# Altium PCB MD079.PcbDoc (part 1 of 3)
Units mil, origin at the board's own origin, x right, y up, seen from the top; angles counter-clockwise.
Board outline 4255 x 2850 mil, 4 copper layers (Top Layer, Ground, Power, Bottom Layer), stack 61.6 mil thick; 171 components, 88 nets, 422 pads, 405 vias.
Unrouted connection lines stored in the file: 3.
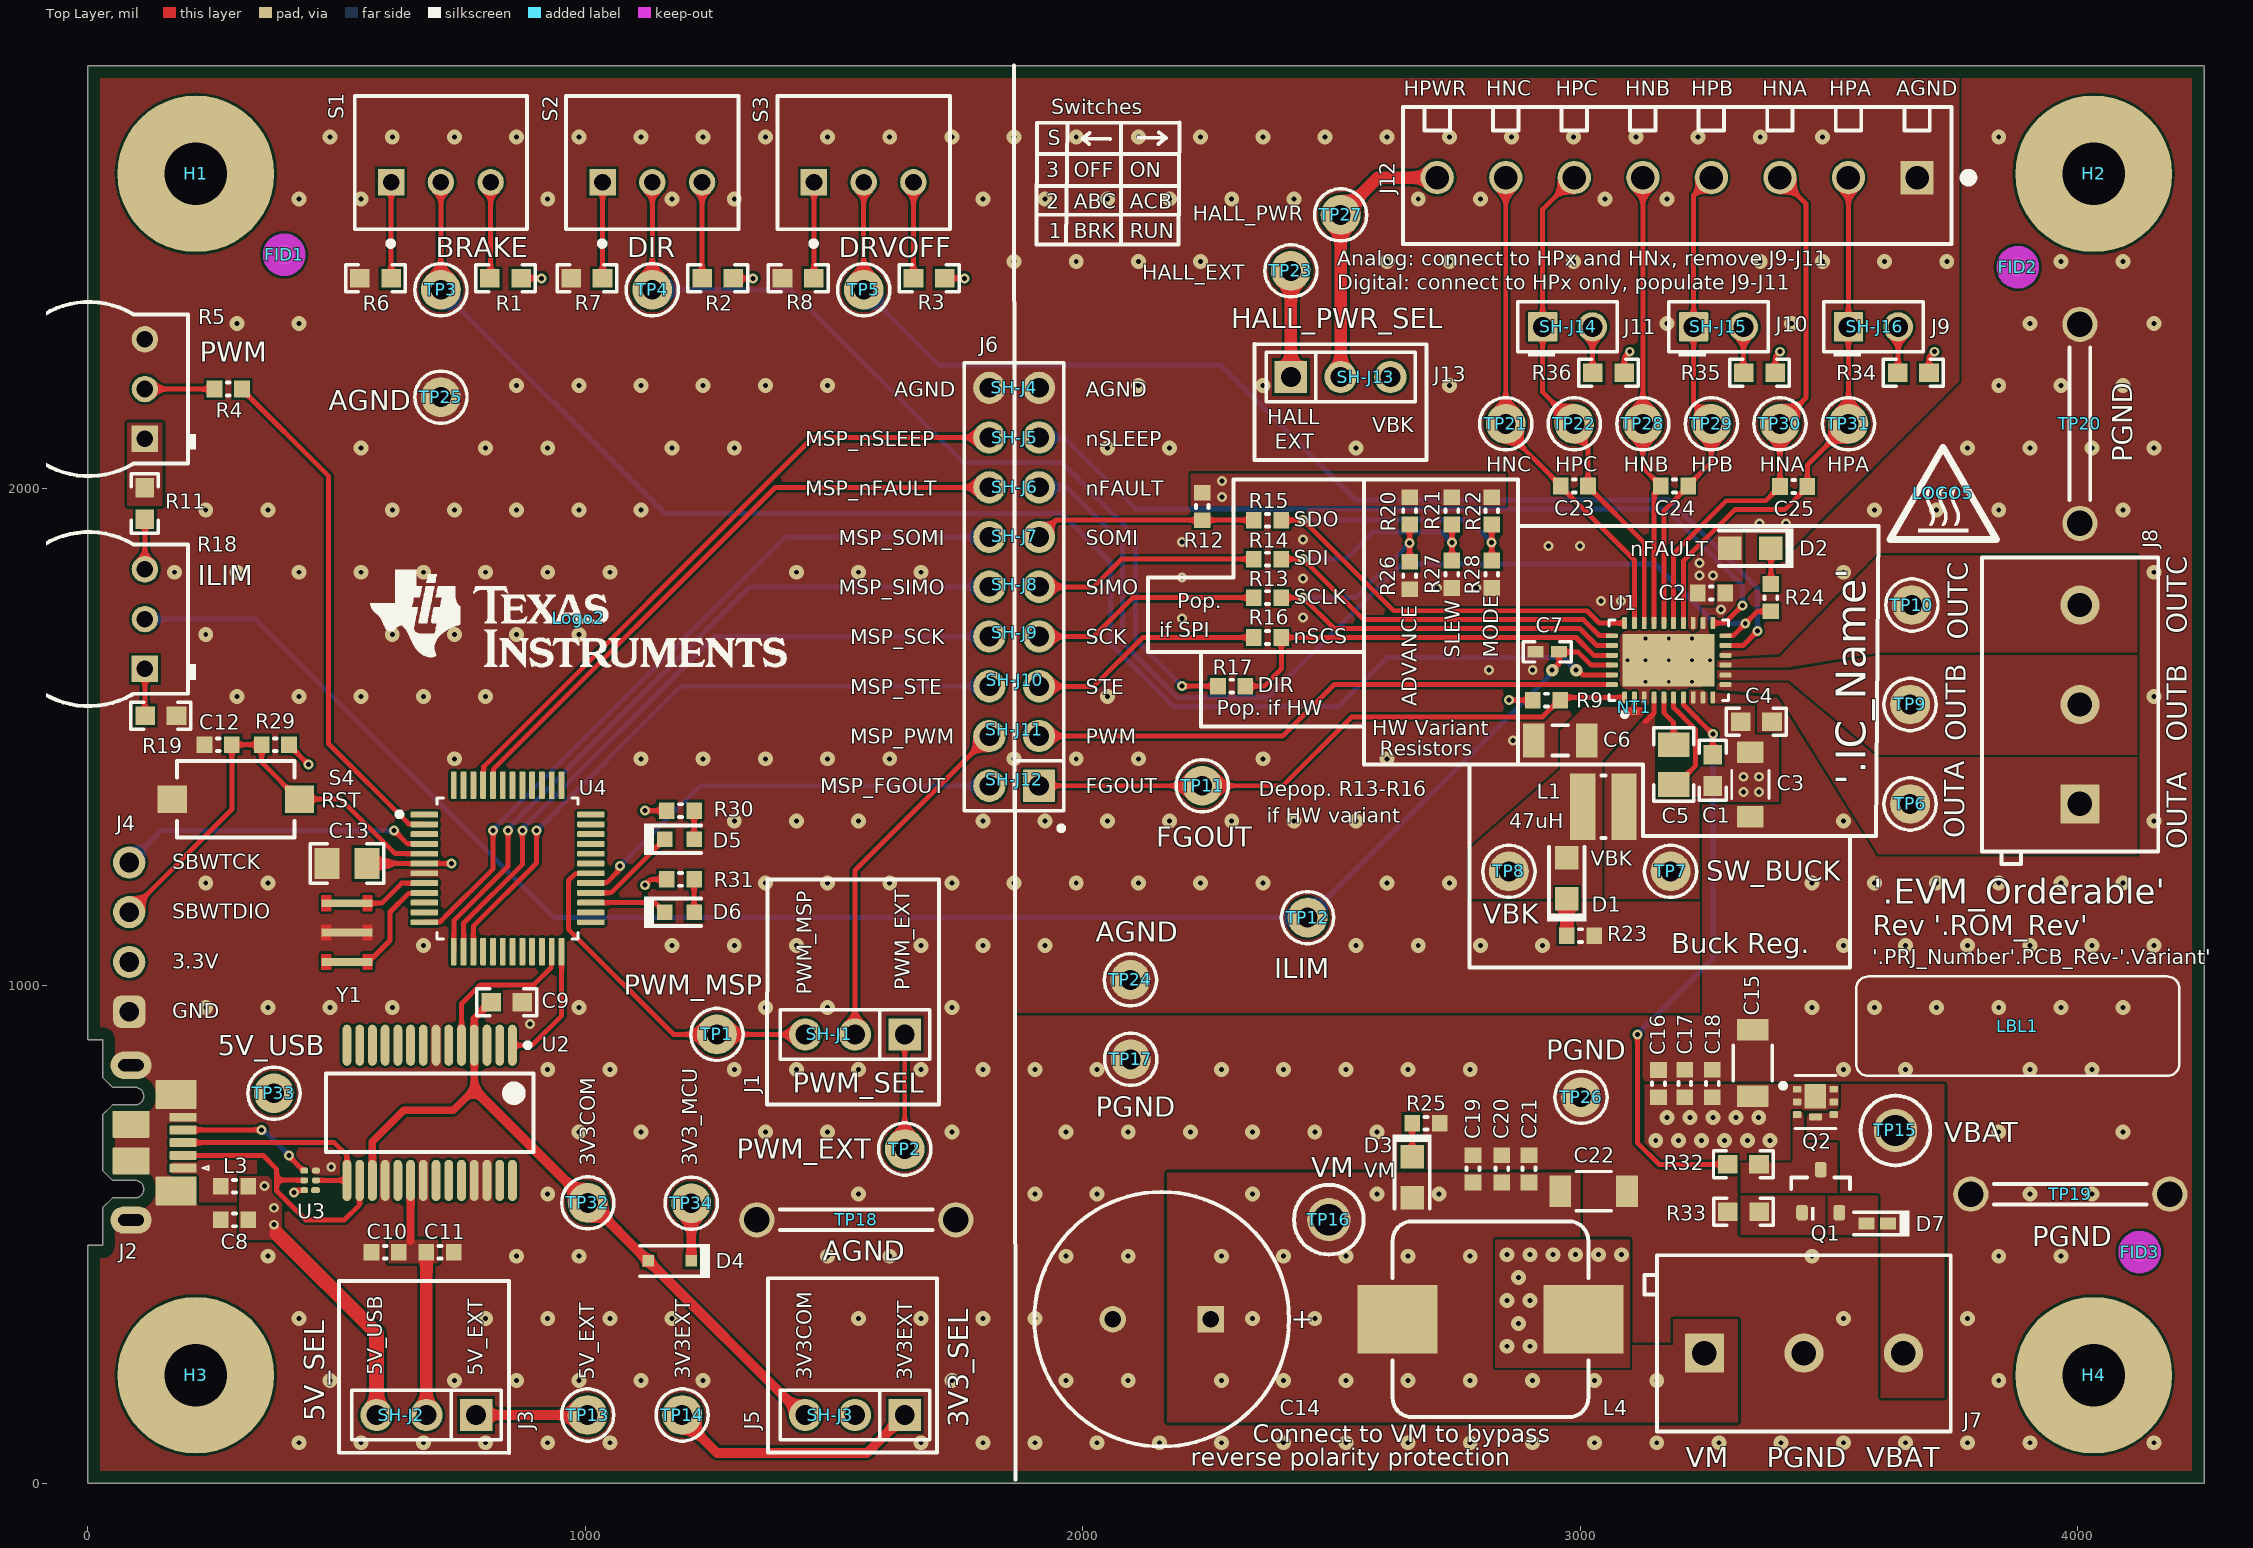
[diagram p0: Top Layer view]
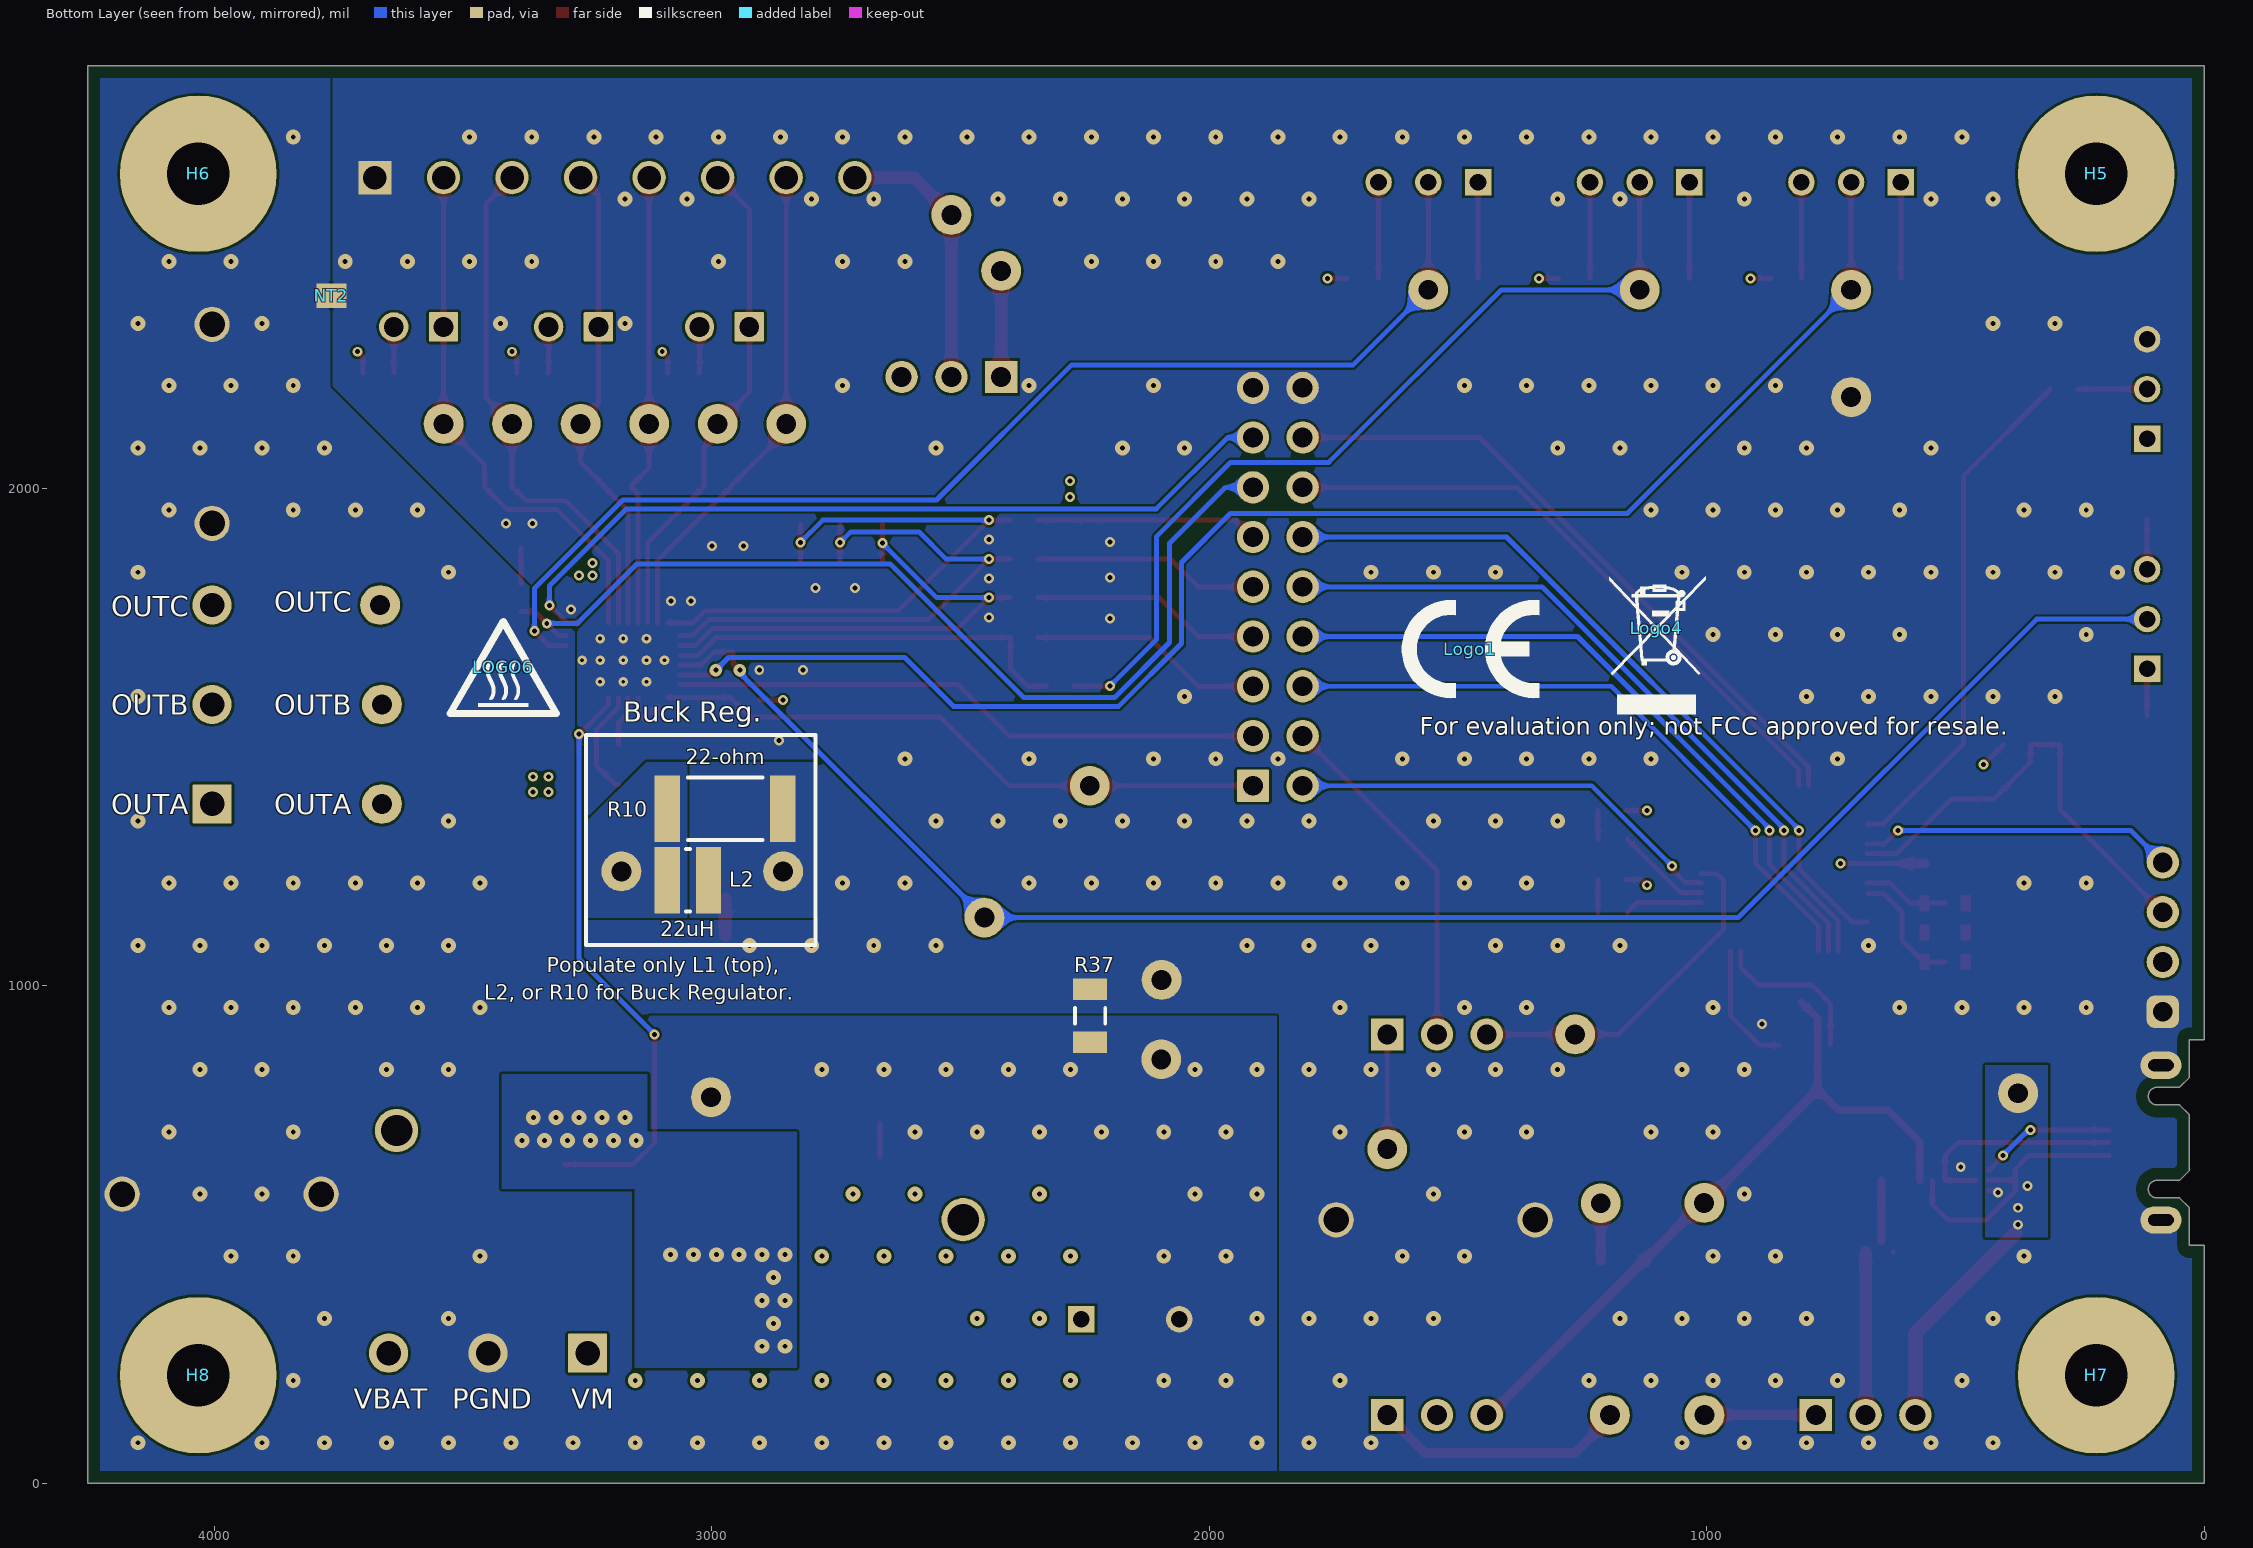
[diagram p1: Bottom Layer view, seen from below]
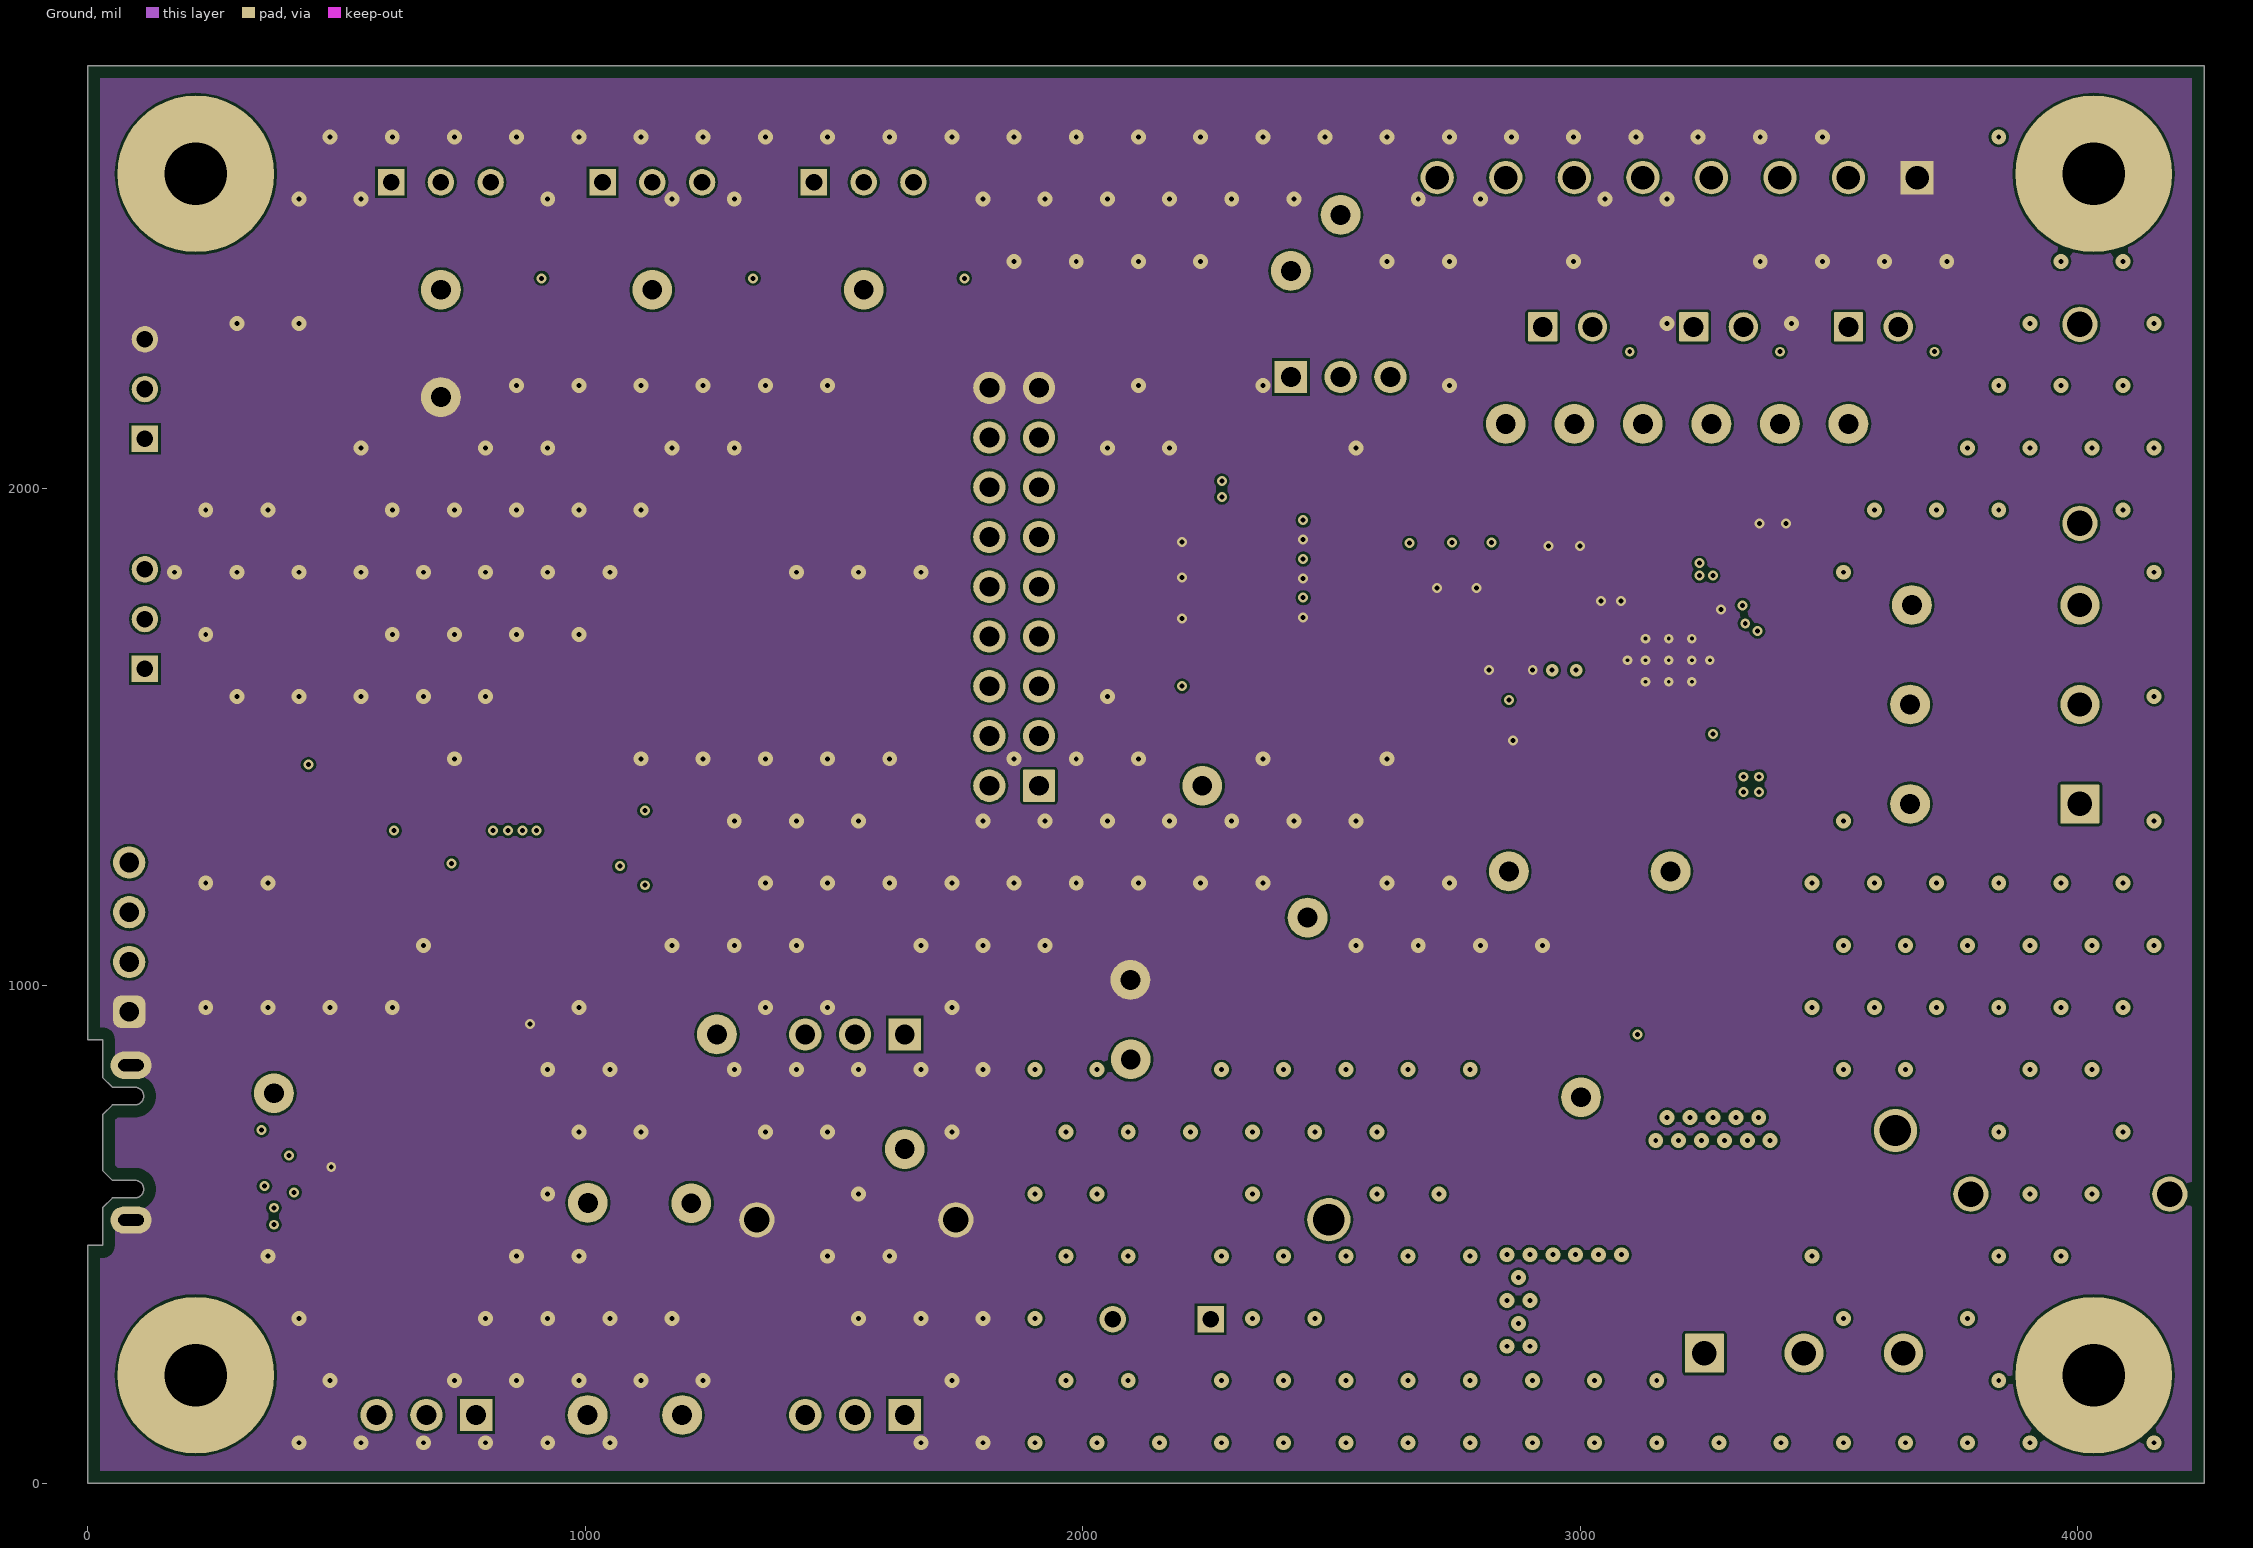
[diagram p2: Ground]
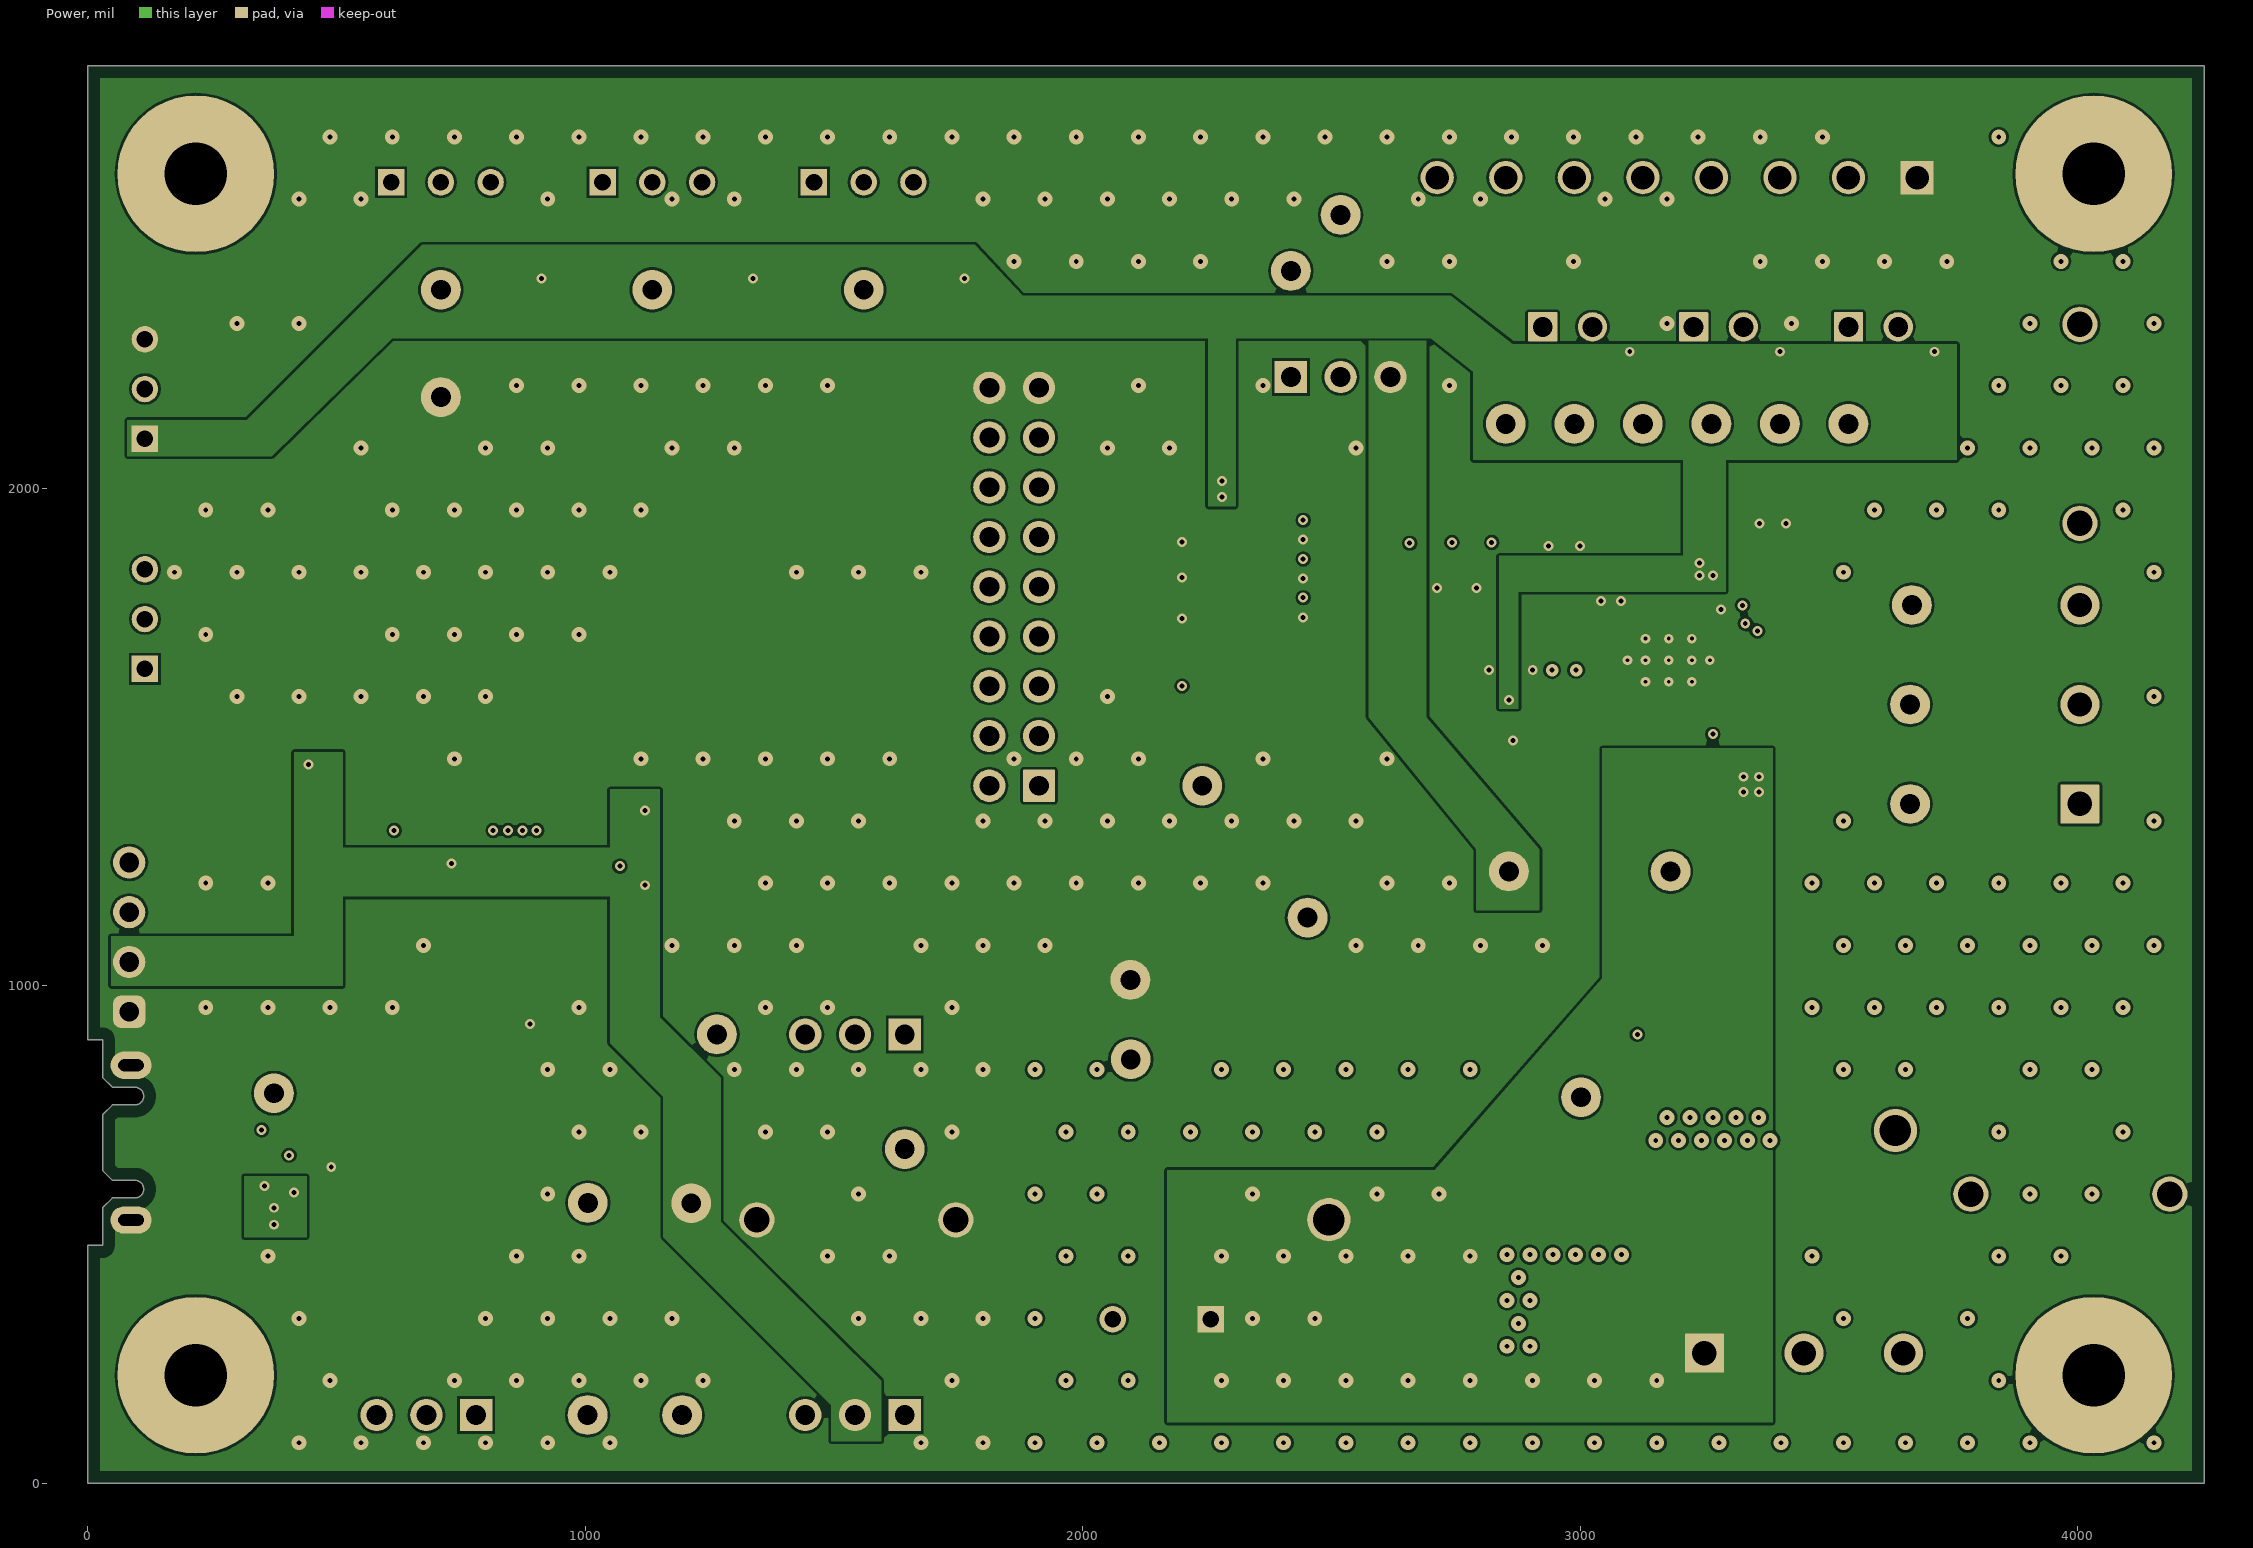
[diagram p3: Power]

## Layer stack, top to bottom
Top Solder: solder mask 0.4, Solder Resist, Dk 3.5
Top Layer: signal copper 1.4
Dielectric 1: prepreg 8, FR-4, Dk 4.2
Ground: signal copper 1.4
Dielectric 2: core 40, FR-4, Dk 4.2
Power: signal copper 1.4
Dielectric 3: prepreg 8, FR-4, Dk 4.2
Bottom Layer: signal copper 1.4
Bottom Solder: solder mask 0.4, Solder Resist, Dk 3.5

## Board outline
0,0 0,478.31 30,478.31 30,554.09 49.68,573.78 94.96,573.78 ccw(c94.81,591.5) 94.96,609.21 49.68,609.21 30,628.9 30,741.1 49.68,760.79 94.96,760.79 ccw(c94.85,778.5) 94.96,796.22 49.68,796.22 30,815.91 30,891.69 0,891.69 0,2850 4255,2850 4255,0

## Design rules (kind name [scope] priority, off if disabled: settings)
AcuteAngle [All] p1: minimum=4.50000000000000E+0001 checktracksonly=FALSE
AssemblyTestPointUsage [All] p1: valid=2
BoardOutlineClearance BoardOutlineClearance_MountingHoles [OnCopper and InComponentClass('Mounting Holes')] p1: gap=39.37 ignorepadtopadclearanceinfootprint=FALSE
BoardOutlineClearance BoardOutlineClearance_Poly [OnCopper and IsPoly] p2: gap=25 ignorepadtopadclearanceinfootprint=FALSE
BoardOutlineClearance [OnCopper and Not InComponentClass('Logo') and not InComponentClass('FiducialMark') and not InRegion(1000,500,4000,800) and not InPoly] p3: gap=30 ignorepadtopadclearanceinfootprint=FALSE
Clearance "Stitching AGND" [IsStitchingVia and InNet('AGND') vs (IsVia and (Not IsStitchingVia)) Or IsPad] p1: gap=70 ignorepadtopadclearanceinfootprint=TRUE
Clearance Clearance_Keepouts [((IsTrack Or IsArc) And Not InPoly) And IsFree and IsKeepOut vs ((IsTrack Or IsArc) And Not InPoly) And IsFree and IsKeepOut] p2: gap=0 ignorepadtopadclearanceinfootprint=FALSE
Clearance Clearance_Poly [InPolygon] p3: gap=5 ignorepadtopadclearanceinfootprint=TRUE
Clearance Clearance_FiducialMark [IsKeepOut and InComponentClass('FiducialMark') vs IsPad and InComponentClass('FiducialMark')] p4: gap=0 ignorepadtopadclearanceinfootprint=FALSE
Clearance [All] p5: gap=7.87 ignorepadtopadclearanceinfootprint=TRUE
ComponentClearance ComponentClearance_MountingHoles_FiducialMarks [InComponentClass('Mounting Holes') vs InComponentClass('FiducialMark')] p1: gap=50 collisioncheckmode=3 verticalgap=10 showdistances=FALSE
ComponentClearance ComponentClearance_Shunt [InComponentClass('Header') vs InComponentClass('Shunt')] p2: gap=0 collisioncheckmode=3 verticalgap=0 showdistances=FALSE
ComponentClearance ComponentClearance_Logo [InComponentClass('Logo')] p3: gap=50 collisioncheckmode=3 verticalgap=10 showdistances=FALSE
ComponentClearance ComponentClearance_ScrewToNut [(HasFootprint('NY PMS 440 0025 PH')) vs (HasFootprint('Keystone_1902C'))] p4: gap=5 collisioncheckmode=3 verticalgap=10 showdistances=FALSE
ComponentClearance ComponentClearance_MountingHoles [InComponentClass('Mounting Holes')] p5: gap=150 collisioncheckmode=3 verticalgap=100000 showdistances=FALSE
ComponentClearance ComponentClearance_SmallPassives [HasFootprint('0201*') or HasFootprint('0402*') or HasFootprint('0508') or HasFootprint('0603*') or HasFootprint('0612') or HasFootprint('0805*') or HasFootprint('0815*') or HasFootprint('0830*') or HasFootprint('1206*') or HasFootprint('1210*') or HasFootprint('1808*') or HasFootprint('1812*') or HasFootprint('1825*') or HasFootprint('2010*') or HasFootprint('2220*') or HasFootprint('2225*') or HasFootprint('2512*') or HasFootprint('2728*') or HasFootprint('3518*') vs HasFootprint('0201*') or HasFootprint('0402*') or HasFootprint('0508') or HasFootprint('0603*') or HasFootprint('0612') or HasFootprint('0805*') or HasFootprint('0815*') or HasFootprint('0830*') or HasFootprint('1206*') or HasFootprint('1210*') or HasFootprint('1808*') or HasFootprint('1812*') or HasFootprint('1825*') or HasFootprint('2010*') or HasFootprint('2220*') or HasFootprint('2225*') or HasFootprint('2512*') or HasFootprint('2728*') or HasFootprint('3518*')] p6: gap=14.96 collisioncheckmode=3 verticalgap=10 showdistances=FALSE
ComponentClearance ComponentClearance_THtoSMT [IsThruComponent vs IsSMTComponent] p7: gap=0 collisioncheckmode=3 verticalgap=0 showdistances=FALSE
ComponentClearance ComponentClearance_THtoTH [IsThruComponent vs IsThruComponent] p8: gap=0 collisioncheckmode=3 verticalgap=0 showdistances=FALSE
ComponentClearance [All] p9: gap=0 collisioncheckmode=3 verticalgap=0 showdistances=FALSE
DiffPairsRouting [All] p1: maxlimit=100 minlimit=10 mostfreqgap=10 toplayer_minwidth=15 toplayer_maxwidth=15 toplayer_prefwidth=15 midlayer1_minwidth=15 midlayer1_maxwidth=15 midlayer1_prefwidth=15 midlayer2_minwidth=15 midlayer2_maxwidth=15 midlayer2_prefwidth=15 bottomlayer_minwidth=15 bottomlayer_maxwidth=15 bottomlayer_prefwidth=15 maxuncoupledlength=1000
FabricationTestPointUsage TestPointUsage [All] p1: valid=2 allowmultiple=FALSE
FabricationTestpoint Testpoint [All] p1: side=3 testpointundercomponent=TRUE minsize=40 maxsize=100 preferedsize=60 minholesize=0 maxholesize=40 preferedholesize=32 testpointgrid=1 allowsidetop=TRUE allowsidebottom=TRUE usegrid=TRUE gridtolerance=0.01
FanoutControl Fanout_LCC [IsLCC] p1: bgadir=Out bgaviamode=Centered fanoutstyle=Auto fanoutdirection=Alternating viagrid=1 // Fanout_LCC (Default Rule)
FanoutControl Fanout_BGA [IsBGA] p2: bgadir=Out bgaviamode=Centered fanoutstyle=Auto fanoutdirection=Alternating viagrid=1 // Fanout_BGA (Default Rule)
FanoutControl Fanout_Default [All] p4: bgadir=Out bgaviamode=Centered fanoutstyle=Auto fanoutdirection=Alternating viagrid=1 // Fanout_Default (Default Rule)
FanoutControl Fanout_Small [(CompPinCount < 5)] p5: bgadir=Out bgaviamode=Centered fanoutstyle=Auto fanoutdirection=OutThenIn viagrid=1 // Fanout_Small (Default Rule)
HoleSize [All] p1: absolutevalues=TRUE maxlimit=200 minlimit=1 maxpercent=80.000 minpercent=20.000
MinimumAnnularRing MinimumAnnularRing_ThermalPadVias [IsVia and InAnyComponent] p1: minimumring=1
MinimumAnnularRing [All] p2: minimumring=1
MinimumSolderMaskSliver MinimumSolderMaskSliver_Logo [InComponentClass('Logo') vs InComponentClass('Logo')] p1: minsoldermaskwidth=0.7
MinimumSolderMaskSliver [All] p2: minsoldermaskwidth=1
PlaneConnect [All] p1: planeconnectstyle=Relief reliefexpansion=10 reliefentries=4 reliefconductorwidth=10 reliefairgap=10
PolygonConnect [All] p1: connectstyle=Direct reliefconductorwidth=10 reliefentries=4 polygonreliefangle="90 Angle" airgapwidth=10
RoutingVias ThermalPadVias [IsVia and InAnyComponent] p1: holewidth=7.87 width=19.68 viastyle="Through Hole" minholewidth=7.87 minwidth=19.68 maxholewidth=12.99 maxwidth=23.62
RoutingVias [All] p2: holewidth=10 width=25 viastyle="Through Hole" minholewidth=7 minwidth=20 maxholewidth=15 maxwidth=30
SilkToBoardRegionClearance [Not ((IsComment or IsDesignator) And (Hide <> 'False')) and not InRegion(1000,500,4000,800)] p1:
SilkToSilkClearance SilkToSilkClearance_Pb-FreeLogo [(HasFootprint('Pb-Free_Overlay_Medium') OR HasFootprint('Pb-Free_Overlay_Small')) vs (HasFootprint('Pb-Free_Overlay_Medium') OR HasFootprint('Pb-Free_Overlay_Small'))] p1: silktosilkclearance=1
SilkToSilkClearance [All] p2: silktosilkclearance=1
SilkToSolderMaskClearance [IsPad] p1: minsilkscreentomaskgap=1 clearancetoexposedcopper=TRUE
SolderMaskExpansion [All] p1: expansion=1.97 istentingtop=FALSE
UnRoutedNet [All] p1: checkbadconnections=TRUE
Width [All] p1: maxlimit=100 minlimit=6 preferedwidth=10 checkconnectedcopper=TRUE
14 further rules are at their usual default settings.

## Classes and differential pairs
component class Label: LBL1
component class "Mounting Holes": H1 H2 H3 H4
component class MD079_INTERFACE: 3V3_EXT C8 C9 C10 C11 C12 C13 D4 D5 D6 J2 J3 J4 J5 J6 L3 R29 R30 R31 S4 SH-J2 SH-J3 SH-J4 SH-J5 SH-J6 SH-J7 SH-J8 SH-J9 SH-J10 SH-J11 SH-J12 TP13 TP14 TP32 TP33 TP34 U2 U3 U4 Y1
component class MD079_CONTROL: J1 R1 R2 R3 R4 R5 R6 R7 R8 S1 S2 S3 SH-J1 TP1 TP2 TP3 TP4 TP5
component class Shunt: SH-J1 SH-J2 SH-J3 SH-J4 SH-J5 SH-J6 SH-J7 SH-J8 SH-J9 SH-J10 SH-J11 SH-J12 SH-J13 SH-J14 SH-J15 SH-J16
component class MD079_POWER_AND_CONNECTORS: AGND1 C14 C15 C16 C17 C18 C19 C20 C21 C22 C23 C24 C25 D7 J7 J8 J9 J10 J11 J12 J13 L4 NT2 PGND PGND2 Q1 Q2 R32 R33 R34 R35 R36 R37 R45 SH-J13 SH-J14 SH-J15 SH-J16 TP15 TP16 TP17 TP18 TP19 TP20 TP21 TP22 TP23 TP24 TP25 TP26 TP27 TP28 TP29 TP30 TP31 vm VM1
component class MD079_DRIVER: 1 A1 B1 C1 C2 C3 C4 C5 C6 C7 D1 D2 D3 D? ILIM1 L1 L2 NT1 R9 R10 R11 R12 R13 R14 R15 R16 R17 R18 R19 R20 R21 R22 R23 R24 R25 R26 R27 R28 TP6 TP7 TP8 TP9 TP10 TP11 TP12 U1
component class Header: J1 J3 J4 J5 J6 J9 J10 J11 J13
component class Logo: Logo2
component class MD079_HARDWARE: FID1 FID2 FID3 H1 H2 H3 H4 H5 H6 H7 H8 LBL1 Logo1 Logo2 Logo3 Logo4 LOGO5 LOGO6 ZZ1 ZZ2 ZZ3 ZZ4
component class FiducialMark: FID1 FID2 FID3
component class AssemblyNote: ZZ1 ZZ2 ZZ3 ZZ4

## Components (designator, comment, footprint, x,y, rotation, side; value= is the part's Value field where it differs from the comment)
C1 "0603YD105KAT2A" 0603 3266.91,1433.54 r270 top value=1uF
C2 "C0603C105K9RACAUTO" 0603L 3264.11,1790 r180 top value=1uF
C3 "C3216X6S2A106K160AC" FP-C3216X6S2A106K160AC_1206-MFG 3342.44,1405 r90 top value=10µF
C4 "GCJ188R72A104KA01D" 0603 3354.41,1531.45 r0 top value=0.1uF
C5 "C2012X7R2A473K125AA" 0805_HV 3188.17,1445 r90 top value=0.047uF
C6 "GRM31CR71A226KE15L" 1206_180L 2960.57,1493.52 r180 top value=22uF
C7 "C1005X5R1A104K050BA" 0402 2934.02,1671.75 r180 top value=0.1uF
C8 "C0603C104K8RACTU" 0603L 295.3,529.83 r180 top value=0.1uF
C9 "C0603C104K8RACTU" 0603 842.5,967.5 r0 top value=0.1uF
C10 "GRM188Z71A475ME15D" 0603L 597.93,464.83 r0 top value=4.7uF
C11 "C0603C104K8RACTU" 0603L 708.38,464.83 r0 top value=0.1uF
C12 "885012206034" 0603L 262.36,1485.08 r180 top value=1000pF
C13 "C0805C105K5RACTU" 0805_HV 521.16,1246.18 r180 top value=1uF
C14 "ELXZ630ELL331MK20S" Chemi-Con_1250x2000 2159.07,330 r180 top value=330uF
C15 "GRM31CR72A105KA01L" 1206_180 3347.22,845.06 r90 top value=1uF
C16 "CGA3E3X7S2A104K080AB" 0603L 3157.89,803.52 r90 top value=0.1uF
C17 "CGA3E2X7R2A103K080AA" 0603L 3210.43,803.77 r90 top value=0.01uF
C18 "06031C102JAT2A" 0603L 3266.18,803.88 r90 top value=1000pF
C19 "06031C102JAT2A" 0603L 2785,632.45 r90 top value=1000pF
C20 "CGA3E2X7R2A103K080AA" 0603L 2842.95,632.45 r90 top value=0.01uF
C21 "CGA3E3X7S2A104K080AB" 0603L 2897.5,632.45 r90 top value=0.1uF
C22 "GRM31CR72A105KA01L" 1206_180 3027.5,587.55 r0 top value=1uF
C23 "0603YC104K4T4A" 0603L 2988.52,2005 r0 top value=0.1uF
C24 "0603YC104K4T4A" 0603L 3189.74,2005 r0 top value=0.1uF
C25 "0603YC104K4T4A" 0603L 3429.47,2004.02 r0 top value=0.1uF
D1 "LTST-C170KGKT" LTST-C170KGKT_Green 2973.39,1216.38 r270 top value=Green
D2 "LTST-C170KRKT" LED_LTST-C170_Red 3342.44,1880 r0 top value=Red
D3 "LTST-C170KGKT" LTST-C170KGKT_Green 2662.52,615.11 r90 top value=Green
D4 "BAT165E6327HTSA1" SOD-323 1170,447.36 r180 top value=40V
D5 "LTST-C190KRKT" LED_LTST-C190_Red 1189.52,1295.15 r180 top value=Red
D6 "LTST-C190GKT" LED_LTST-C190 1189.52,1148.04 r180 top value=Green
D7 "BAS516,115" SOD-523 3597.5,522.5 r180 top value=100V
FID1 "Fiducial" Fiducial10-20 395,2470 r0 top
FID2 "Fiducial" Fiducial10-20 3880,2445 r0 top
FID3 "Fiducial" Fiducial10-20 4125,465 r0 top
H1 "NY PMS 440 0025 PH" "NY PMS 440 0025 PH" 217.5,2632.5 r0 top
H2 "NY PMS 440 0025 PH" "NY PMS 440 0025 PH" 4032.5,2632.5 r0 top
H3 "NY PMS 440 0025 PH" "NY PMS 440 0025 PH" 217.5,217.5 r0 top
H4 "NY PMS 440 0025 PH" "NY PMS 440 0025 PH" 4032.5,217.5 r0 top
H5 "Nut" Keystone_1902C 217.5,2632.5 r180 bottom
H6 "Nut" Keystone_1902C 4032.5,2632.5 r180 bottom
H7 "Nut" Keystone_1902C 217.5,217.5 r180 bottom
H8 "Nut" Keystone_1902C 4032.5,217.5 r180 bottom
J1 "Header_3x1" PBC03SAAN 1542.5,902.5 r180 top
J2 "1051640001" Molex_1051640001 30,685 r270 top
J3 "Header_3x1" PBC03SAAN 680.89,137.5 r180 top
J4 "TSW-104-07-G-S" TSW-104-07-G-S 83.45,1098.24 r90 top
J5 "Header_3x1" PBC03SAAN 1542.5,137.5 r180 top
J6 "TSW-109-07-G-D" Samtec_TSW-109-07-G-D 1862.5,1802.5 r90 top
J7 "MOTOR_OUT" On-Shore_ED120_3DS 3450,261.84 r0 top
J8 "MOTOR_OUT" On-Shore_ED120_3DS 4005,1565.83 r90 top
J9 "PEC02SAAN" CONN_PEC02SAAN 3589.65,2325 r0 top
J10 "PEC02SAAN" CONN_PEC02SAAN 3278.33,2325 r0 top
J11 "PEC02SAAN" CONN_PEC02SAAN 2975,2325 r0 top
J12 "OSTTE080161" On-Shore_OSTTE080161 3195.22,2625 r180 top
J13 "HALL_PWR_SEL" PBC03SAAN 2518.77,2224.15 r0 top
L1 "78438335470" WE-MAIA_3015 3047.07,1360.21 r180 top value=47uH
L2 "78438335220" WE-MAIA_3015 3048.37,1212.41 r180 bottom value=22uH
L3 "BLM18SG121TZ1D" 0603L 295,597.5 r180 top
L4 "SRP1038A-1R0M" SRP1038A 2820,330 r180 top value=1uH
LBL1 "THT-14-423-10" Label_650x200 3880,919.08 r0 top
Logo1 "CE Mark" CE_Mark_5mm 1475.24,1677.22 r180 bottom
Logo2 "Texas Instruments" TI_Stacked_Overlay_Small 986.72,1739.02 r0 top
Logo3 "FCC disclaimer" FCC_disclaimer 2440,3370 r90 top
Logo4 "WEEE logo" WEEE_Minimum 1101.22,1718.72 r180 bottom
LOGO5 "CAUTION HOT SURFACE" IEC_HotSurface_Small 3729.98,1990.63 r0 top
LOGO6 "CAUTION HOT SURFACE" IEC_HotSurface_Small 3419.55,1640.41 r180 bottom
NT1 "Net-Tie" Net-Tie_10mil 3109.32,1560.44 r270 top net-tie
NT2 "Net-Tie" Net-Tie_50milWide_30milLong 3765,2387.5 r0 bottom net-tie
Q1 "FMMT620TA" SOT-23L 3483.75,587.55 r90 top value="80 V"
Q2 "BUK9D23-40EX" FP-BUK9D23-40EX_SOT1220-MFG 3473.19,766.91 r0 top
R1 "RC0603FR-0710KL" 0603 840,2422.5 r0 top value=10.0k
R2 "RC0603FR-0710KL" 0603 1266.52,2422.52 r0 top value=10.0k
R3 "RC0603FR-0710KL" 0603 1691.66,2422.64 r0 top value=10.0k
R4 "ERJ-3GEY0R00V" 0603L 282.5,2200 r180 top value=0
R5 "3352T-1-253LF" Bourns_3352T 115,2200 r90 top value=25k
R6 "RC0603FR-0710KL" 0603 578.41,2422.48 r0 top value=10.0k
R7 "RC0603FR-0710KL" 0603 1003.46,2422.52 r0 top value=10.0k
R8 "RC0603FR-0710KL" 0603 1428.34,2422.64 r0 top value=10.0k
R9 "CRCW06035K10JNEA" 0603L 2932.5,1574.6 r180 top value=5.1k
R10 "CRCW251222R0JNEGHP" 2512 2973.57,1356.21 r180 bottom value=22
R11 "RC0603FR-0751K1L" 0603 115,1970 r90 top value=51.1k
R12 "CRCW06035K10JNEA" 0603L 2240.61,1963.92 r90 top value=5.1k
R13 "ERJ-3GEY0R00V" 0603L 2371.95,1780.64 r0 top value=0
R14 "ERJ-3GEY0R00V" 0603L 2371.95,1858.14 r0 top value=0
R15 "ERJ-3GEY0R00V" 0603L 2371.95,1936.33 r0 top value=0
R16 "ERJ-3GEY0R00V" 0603L 2371.95,1700.64 r0 top value=0
R17 "ERJ-3GEY0R00V" 0603L 2299.63,1602.81 r0 top value=0
R18 "3352T-1-103LF" Bourns_3352T 115,1737.5 r90 top value=10k
R19 "RC0603FR-0741K2L" 0603 147.01,1543.35 r180 top value=41.2k
R20 "ERA-3AEB104V" 0603L 2657.5,1955.2 r90 top value=100k
R21 "ERJ-3GEY0R00V" 0603L 2742.5,1955.2 r90 top value=0
R22 "ERJ-3EKF2202V" 0603L 2822.5,1955.2 r90 top value=22.0k
R23 "RC0603FR-07330RL" 0603L 3000.95,1101.26 r180 top value=330
R24 "RC0603JR-071KL" 0603L 3383.78,1780.64 r90 top value=1.0k
R25 "RT0603BRD074K7L" 0603L 2690.28,724.11 r180 top value=4.70k
R26 "ERJ-3GEY0R00V" 0603L 2657.5,1824.94 r90 top value=0
R27 "ERJ-3GEY0R00V" 0603L 2742.5,1827.74 r90 top value=0
R28 "ERA-3AEB104V" 0603L 2822.5,1827.74 r90 top value=100k
R29 "RC0603JR-0747KL" 0603L 377.2,1485.08 r0 top value=47k
R30 "RC0603JR-07470RL" 0603L 1191.51,1352.5 r180 top value=470
R31 "RC0603JR-07470RL" 0603L 1191.51,1214.26 r180 top value=470
R32 "RC0603FR-0710KL" 0603 3328.33,641.48 r0 top value=10.0k
R33 "RC0603FR-0710KL" 0603 3328.5,545.84 r0 top value=10.0k
R34 "RC0603FR-0710KL" 0603 3670,2232.5 r180 top value=10.0k
R35 "RC0603FR-0710KL" 0603 3361,2232.5 r180 top value=10.0k
R36 "RC0603FR-0710KL" 0603 3057.5,2232.5 r180 top value=10.0k
R37 "RCA12060000ZSEA" 1206L 2240,940 r270 bottom value=0
S1 "SW_SPDT_COM2_1_3" SW_B12AP 710,2655 r90 top
S2 "SW_SPDT_COM2_1_3" SW_B12AP 1135,2655 r90 top
S3 "SW_SPDT_COM2_1_3" SW_B12AP 1560,2655 r90 top
S4 "SW_SPST-single" SW_434121025816 297.8,1375.44 r180 top
SH-J1 "SNT-100-BK-G" SNT-100-BK-G 1491.17,902.5 r180 top value=1x2
SH-J2 "SNT-100-BK-G" SNT-100-BK-G 630.83,137.5 r180 top value=1x2
SH-J3 "SNT-100-BK-G" SNT-100-BK-G 1492.5,137.5 r180 top value=1x2
SH-J4 "SNT-100-BK-G" SNT-100-BK-G 1862.5,2202.5 r180 top value=1x2
SH-J5 "SNT-100-BK-G" SNT-100-BK-G 1863.16,2102.5 r180 top value=1x2
SH-J6 "SNT-100-BK-G" SNT-100-BK-G 1863.25,2002.5 r180 top value=1x2
SH-J7 "SNT-100-BK-G" SNT-100-BK-G 1863.33,1904 r180 top value=1x2
SH-J8 "SNT-100-BK-G" SNT-100-BK-G 1863.42,1806.72 r180 top value=1x2
SH-J9 "SNT-100-BK-G" SNT-100-BK-G 1863.5,1710.3 r180 top value=1x2
SH-J10 "SNT-100-BK-G" SNT-100-BK-G 1863.59,1615 r180 top value=1x2
SH-J11 "SNT-100-BK-G" SNT-100-BK-G 1862.5,1515 r180 top value=1x2
SH-J12 "SNT-100-BK-G" SNT-100-BK-G 1862.5,1415 r180 top value=1x2
SH-J13 "SNT-100-BK-G" SNT-100-BK-G 2569.13,2224.15 r180 top value=1x2
SH-J14 "SNT-100-BK-G" SNT-100-BK-G 2976.32,2325 r180 top value=1x2
SH-J15 "SNT-100-BK-G" SNT-100-BK-G 3277.5,2325 r180 top value=1x2
SH-J16 "SNT-100-BK-G" SNT-100-BK-G 3592.15,2325 r180 top value=1x2
TP1 "PWM_MSP" Keystone5002 1264.93,902.5 r90 top
TP2 "PWM_EXT" Keystone5002 1642.5,672.2 r90 top
TP3 "BRAKE" Keystone5002 710,2399.51 r90 top
TP4 "DIR" Keystone5002 1135,2399.51 r90 top
TP5 "DRVOFF" Keystone5002 1560,2399.51 r90 top
TP6 "OUTA" Keystone5000 3663.5,1365.83 r90 top
TP7 "SW_BUCK" Keystone5000 3182.09,1230.21 r90 top
TP8 "VBK" Keystone5000 2857.07,1230.21 r90 top
TP9 "OUTB" Keystone5000 3663.5,1565.83 r90 top
TP10 "OUTC" Keystone5000 3667.15,1765.83 r90 top
TP11 "FGOUT" Keystone5002 2240.64,1402.5 r90 top
TP12 "ILIM" Keystone5002 2452.32,1137.5 r90 top
TP13 "5V_EXT" Keystone5000 1005.02,137.5 r90 top
TP14 "3V3EXT" Keystone5000 1195,137.5 r90 top
TP15 "VBAT" Keystone5005 3634.05,709.46 r180 top
TP16 "VM" Keystone5005 2495,530.11 r0 top
TP17 "PGND" Keystone5001 2096.74,852.5 r90 top
TP18 "AGND" Harwin_D3082-05 1545.19,529.83 r180 top
TP19 "PGND" Harwin_D3082-05 3985.61,581.39 r180 top
TP20 "PGND" Harwin_D3082-05 4005,2130 r90 top
TP21 "HNC" Keystone5002 2850.73,2130 r90 top
TP22 "HPC" Keystone5002 2988.52,2130 r90 top
TP23 "HALL_EXT" Keystone5000 2418.77,2437.5 r90 top
TP24 "AGND" Keystone5001 2096.19,1012.13 r90 top
TP25 "AGND" Keystone5001 710,2183.75 r90 top
TP26 "PGND" Keystone5001 3002.02,776.25 r90 top
TP27 "HALL_PWR" Keystone5000 2518.77,2550 r90 top
TP28 "HNB" Keystone5002 3126.32,2130 r90 top
TP29 "HPB" Keystone5002 3264.11,2130 r90 top
TP30 "HNA" Keystone5002 3401.91,2130 r90 top
TP31 "HPA" Keystone5002 3539.65,2130 r270 top
TP32 "3V3COM" Keystone5000 1005.39,563.83 r90 top
TP33 "5V_USB" Keystone5000 374.4,784.37 r90 top
TP34 "3V3_MCU" Keystone5000 1213.31,563.23 r90 top
U1 "MCT8315Z0RRRYR" RRY0032A-MFG 3178.33,1654.84 r90 top
U2 "FT232RL" SSOP28_N 687.5,745 r270 top
U3 "TPD4E004DRYR" DRY0006A 447.16,609.17 r180 top
U4 "MSP430FR2355TPTR" PT0048A-MFG 844.22,1236.34 r0 top
Y1 "CSTCR4M00G55B-R0" Murata_CSTCR_G 521.16,1107.3 r270 top
ZZ1 "This Assembly Note is for PCB labels only" AssemblyNoteLabel -624.68,3416.2 r0 top
ZZ2 "These assemblies are ESD sensitive, ESD precautions shall be observed." AssemblyNote -624.68,3307.32 r0 top
ZZ3 "These assemblies must be clean and free from flux and all contaminants. Use of no clean flux is not acceptable." AssemblyNote -624.68,3218.76 r0 top
ZZ4 "These assemblies must comply with workmanship standards IPC-A-610 Class 2, unless otherwise specified." AssemblyNote -624.68,3130.2 r0 top

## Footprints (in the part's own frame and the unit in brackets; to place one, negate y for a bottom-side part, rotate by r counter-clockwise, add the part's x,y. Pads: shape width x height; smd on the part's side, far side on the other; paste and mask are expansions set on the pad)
0402 [mm] "0402 from SM-752 data"
  rect 0.8x0.6 smd: 1(-0.6,0) 2(0.6,0)
  silkscreen extent -1.22,-0.52 1.22,0.52, body extent -0.55,-0.3 0.55,0.3, height 0.6
0603 [mm] "0603 from SM-752 data"
  rect 1x0.95 smd: 1(-0.8,0) 2(0.8,0)
  silkscreen extent -1.52,-0.69 1.52,0.69, body extent -0.87,-0.47 0.87,0.47, height 1
0603L [mm] "0603 from SM-752 data"
  rect 0.8x0.85 smd: 1(-0.7,0) 2(0.7,0)
  silkscreen extent -0.07,-0.33 0.07,0.33, body extent -0.87,-0.47 0.87,0.47, height 1
0805_HV [mil] "0805 with 30mil clearance between pads"
  rect 50x63 smd: 1(-40,0) 2(40,0)
  silkscreen extent -74,-40 74,40, body extent -43,-29 43,29, height 57
1206_180 [mm] "1206_180"
  rect 1.1x1.6 smd: 1(-1.7,0) 2(1.7,0)
  silkscreen extent -0.9,-1 0.9,1, body extent -1.75,-0.95 1.75,0.95, height 1.8
1206_180L [mm] "1206_180"
  rect 1.1x1.75 smd: 1(-1.35,0) 2(1.35,0)
  silkscreen extent -0.4,-0.77 0.4,0.77, body extent -1.75,-0.95 1.75,0.95, height 1.8
1206L [mm] "1206 from SM-752 data"
  rect 1.1x1.75 smd: 1(-1.35,0) 2(1.35,0)
  silkscreen extent -0.4,-0.77 0.4,0.77, body extent -1.7,-0.9 1.7,0.9, height 1.35
2512 [mm] "Chip Resistor, Body 6.3x3.2mm, IPC Medium Density"
  rect 1.3x3.4 smd: 1(-2.95,0) 2(2.95,0)
  silkscreen extent -1.9,-1.6 1.9,1.6, body extent -3.22,-1.67 3.22,1.67, height 0.71
AssemblyNote [mil] "Assembly Note"
AssemblyNoteLabel [mil] "Assembly Note for PCB Labels"
Bourns_3352T [mm] "TH, 3-Leads, Body 9.53x8.89mm, Pitch 2.54mm"
  rect 1.35x1.35 hole 0.85: 1(-2.54,0)
  round 1.35 hole 0.85: 2(0,0) 3(2.54,0)
  silkscreen extent -4.44,-2.6 4.44,7.31, body extent -4.44,-2.21 4.45,7.32, height 3.81
CE_Mark_5mm [mil] "Minimum text height for CE Mark"
  silkscreen extent -138,-98 138,98
Chemi-Con_1250x2000 [mm] "TH, 2-Leads, Dia 12.5mm, Lead Sapcing 5mm"
  rect 1.35x1.35 hole 0.85: 1(-2.5,0)
  round 1.35 hole 0.85: 2(2.5,0)
  silkscreen extent -6.5,-6.5 6.5,6.5, body extent -6.5,-6.5 6.51,6.5, height 21.5
CONN_PEC02SAAN [mm] "SULLINS"
  rrect7% 1.5x1.5 hole 1.016: 1(-1.27,0)
  round 1.5 hole 1.016: 2(1.27,0)
  silkscreen extent -2.54,-1.52 2.54,1.27, body extent -2.54,-1.27 2.54,1.27, height 8.38
DRY0006A [mm] "USON-6"
  rrect67% 0.45x0.3 smd paste-0.05 mask-0.05: 1(-0.275,0.5)
  rrect67% 0.4x0.3 smd paste-0.05 mask-0.05: 2(-0.3,0) 3(-0.3,-0.5) 4(0.3,-0.5) 5(0.3,0) 6(0.3,0.5)
  body extent -0.5,-0.72 0.5,0.73, height 0.58
FCC_disclaimer [mil]
Fiducial10-20 [mm]
  round 1 smd mask+0.5: 1(0,0)
  Top Layer keep-out circle w1.178: c0,0 r0.5
FP-BUK9D23-40EX_SOT1220-MFG [mm]
  rrect29% 0.43x0.35 smd paste-1000 mask+0: 1(-0.935,0.65) 2(-0.935,0) 3(-0.935,-0.65) 4(0.935,-0.65) 5(0.935,0) 6(0.935,0.65)
  rrect9% 1.1x1.25 smd paste-1000 mask+0: 7(0,0.285)
  rrect29% 0.66x0.35 smd paste-1000 mask+0: 8(0,-0.775)
  silkscreen extent -1.77,-1.35 1.05,1.35, body extent -1.25,-1.15 1.25,1.15, height 0.25
FP-C3216X6S2A106K160AC_1206-MFG [mm]
  rrect9% 1.1x1.35 smd paste+0 mask+0: 1(-1.65,0) 2(1.65,0)
  silkscreen extent -0.72,-0.95 0.72,0.95, body extent -2.3,-1.05 2.3,1.05, height 0.25
Harwin_D3082-05 [mm] "Shorting Plug, 10.16mm spacing, TH"
  round 1.8 hole 1.3: 1(-5.08,0) 2(5.08,0)
  silkscreen extent -3.9,-0.53 3.9,0.53, body extent -5.6,-0.52 5.61,0.52, height 6.63
IEC_HotSurface_Small [mil]
  silkscreen extent -107,-93 107,92
Keystone5000 [mil] "For Keystone 500x miniature loop terminals"
  round 80 hole 40: 1(0,0)
  silkscreen extent -52,-52 52,52, body extent -49,-49 49,49, height 182
Keystone5001 [mil] "For Keystone 500x miniature loop terminals"
  round 80 hole 40: 1(0,0)
  silkscreen extent -52,-52 52,52, body extent -49,-49 49,49, height 182
Keystone5002 [mil] "For Keystone 500x miniature loop terminals"
  round 80 hole 40: 1(0,0)
  silkscreen extent -52,-52 52,52, body extent -49,-49 49,49, height 182
Keystone5005 [mil] "Keystone Compact loops"
  round 87 hole 63: 1(0,0)
  silkscreen extent -70,-70 70,70, body extent -63,-63 62,63, height 225
Keystone_1902C [mil] "Hex Standoff, 4-40 threaded, nylon"
  round 1 on Mech4: 0(0,0)
  body extent -145,-126 146,126, height 501
Label_650x200 [mil] "Thermal Transfer Label"
  round 1 on Mech13: 0(0,0)
  silkscreen extent -325,-100 325,100, body extent -325,-100 325,100, height 1
LED_LTST-C170_Red [mm] "LITE-ON"
  rect 1.2x1.2 smd: 1(-1.05,0) 2(1.05,0)
  silkscreen extent -1.6,-1 2.2,1, body extent -1.05,-0.67 1.05,0.67, height 1.1
LED_LTST-C190 [mm] "Lite-On"
  rect 0.8x0.8 smd: 1(-0.75,0) 2(0.75,0)
  silkscreen extent -1.1,-0.8 1.8,0.8, body extent -0.85,-0.45 0.85,0.45, height 0.9
LED_LTST-C190_Red [mm] "Lite-On"
  rect 0.8x0.8 smd: 1(-0.75,0) 2(0.75,0)
  silkscreen extent -1.1,-0.8 1.8,0.8, body extent -0.85,-0.45 0.85,0.45, height 0.9
LTST-C170KGKT_Green [mm] "LITE-ON"
  rect 1.2x1.2 smd: 1(-1.05,0) 2(1.05,0)
  silkscreen extent -1.6,-1 2.2,1, body extent -1.05,-0.67 1.05,0.67, height 1.1
Molex_1051640001 [mm] "Receptacle, USB 2.0, Micro B, 5 Pos, 0.65mm Pitch, R/A, SMT"
  rrect22% 0.45x1.38 smd: 1(1.3,4.11) 2(0.65,4.11) 3(0,4.11) 4(-0.65,4.11) 5(-1.3,4.11)
  rrect7% 1.475x2.1 smd: 6(-2.462,3.75) 11(2.462,3.75)
  rrect100% 1.4x2.1 hole 0.6 slot 1.3 at 90 deg: 7(-3.95,1.45) 10(3.95,1.45)
  rrect7% 1.375x1.9 smd: 8(-0.937,1.45) 9(0.937,1.45)
  silkscreen extent 1.2,5.1 1.4,5.4, body extent -4.1,-0.7 4.1,4.47, height 2.45
Murata_CSTCR_G [mm] "Murata"
  rect 0.4x2.6 smd: 1(-1.5,0) 2(0,0) 3(1.5,0)
  Top Layer region: -0.4,0.8 0.4,0.8 0.4,1.3 -0.4,1.3
  Top Layer region: -0.4,-1.301 -0.4,-0.801 0.4,-0.801 0.4,-1.301
  Top Layer region: -1.9,0.8 -1.1,0.8 -1.1,1.3 -1.9,1.3
  Top Layer region: -1.9,-1.301 -1.9,-0.801 -1.1,-0.801 -1.1,-1.301
  Top Layer region: 1.1,0.8 1.9,0.8 1.9,1.3 1.1,1.3
  Top Layer region: 1.1,-1.301 1.1,-0.801 1.9,-0.801 1.9,-1.301
  body extent -2.25,-1 2.25,1, height 1.16
Net-Tie_10mil [mil] "10mil net tie, no solder mask opening, no solder paste"
  rect 10x10 smd paste-5 mask-5: 1(-10,0) 2(10,0)
  Top Layer region: -6,5 6,5 6,-5 -6,-5
Net-Tie_50milWide_30milLong [mil] "50mil net tie, no solder mask opening, no solder paste"
  rect 30x50 smd paste-20 mask-20: 1(-15,0) 2(15,0)
"NY PMS 440 0025 PH" [mm] "4-40 nylon screw and mounting hole"
  round 8 hole 3.2: 1(0,0)
  body extent -3.3,-3.3 3.3,3.3, height 2.69
On-Shore_ED120_3DS [mm] "ONSHORE"
  rrect5% 2x2 hole 1.25: 1(-5.08,0)
  round 2 hole 1.25: 2(0,0) 3(5.08,0)
  silkscreen extent -8.14,-4 7.5,5, body extent -8.32,-4 7.62,5, height 13
On-Shore_OSTTE080161 [mm] "Term Blk 8x1"
  rect 1.7x1.7 hole 1.2: 1(-12.25,0)
  round 1.7 hole 1.2: 2(-8.75,0) 3(-5.25,0) 4(-1.75,0) 5(1.75,0) 6(5.25,0) 7(8.75,0) 8(12.25,0)
  silkscreen extent -14.98,-3.6 14,3.4, body extent -14,-3.6 14,3.4, height 8.4
PBC03SAAN [mm] "Sullins 100mil, 1x3, 230 mil above insulator"
  rect 1.65x1.65 hole 1.016: 1(-2.54,0)
  round 1.65 hole 1.016: 2(0,0) 3(2.54,0)
  silkscreen extent -3.81,-1.27 3.81,1.27, body extent -3.81,-1.27 3.81,1.27, height 8.38
PT0048A-MFG [mm]
  rrect33% 1.4x0.3 smd paste-1000 mask+0: 1(-4.25,2.75) 2(-4.25,2.25) 3(-4.25,1.75) 4(-4.25,1.25) 5(-4.25,0.75) 6(-4.25,0.25) 7(-4.25,-0.25) 8(-4.25,-0.75) 9(-4.25,-1.25) 10(-4.25,-1.75) 11(-4.25,-2.25) 12(-4.25,-2.75) 25(4.25,-2.75) 26(4.25,-2.25) 27(4.25,-1.75) 28(4.25,-1.25) 29(4.25,-0.75) 30(4.25,-0.25) 31(4.25,0.25) 32(4.25,0.75) 33(4.25,1.25) 34(4.25,1.75) 35(4.25,2.25) 36(4.25,2.75)
  rrect33% 0.3x1.4 smd paste-1000 mask+0: 13(-2.75,-4.25) 14(-2.25,-4.25) 15(-1.75,-4.25) 16(-1.25,-4.25) 17(-0.75,-4.25) 18(-0.25,-4.25) 19(0.25,-4.25) 20(0.75,-4.25) 21(1.25,-4.25) 22(1.75,-4.25) 23(2.25,-4.25) 24(2.75,-4.25) 37(2.75,4.25) 38(2.25,4.25) 39(1.75,4.25) 40(1.25,4.25) 41(0.75,4.25) 42(0.25,4.25) 43(-0.25,4.25) 44(-0.75,4.25) 45(-1.25,4.25) 46(-1.75,4.25) 47(-2.25,4.25) 48(-2.75,4.25)
  silkscreen extent -5.65,-3.6 3.6,3.6, body extent -5.05,-5.05 5.05,5.05, height 0.25
RRY0032A-MFG [mm]
  rrect40% 0.6x0.25 smd paste+0 mask+0: 1(-1.9,2.25) 2(-1.9,1.75) 3(-1.9,1.25) 4(-1.9,0.75) 5(-1.9,0.25) 6(-1.9,-0.25) 7(-1.9,-0.75) 8(-1.9,-1.25) 9(-1.9,-1.75) 10(-1.9,-2.25) 17(1.9,-2.25) 18(1.9,-1.75) 19(1.9,-1.25) 20(1.9,-0.75) 21(1.9,-0.25) 22(1.9,0.25) 23(1.9,0.75) 24(1.9,1.25) 25(1.9,1.75) 26(1.9,2.25)
  rrect40% 0.25x0.6 smd paste+0 mask+0: 11(-1.25,-2.9) 12(-0.75,-2.9) 13(-0.25,-2.9) 14(0.25,-2.9) 15(0.75,-2.9) 16(1.25,-2.9) 27(1.25,2.9) 28(0.75,2.9) 29(0.25,2.9) 30(-0.25,2.9) 31(-0.75,2.9) 32(-1.25,2.9)
  rrect4% 2.7x4.7 smd paste-1000 mask+0: 33(0,0)
  silkscreen extent -2.87,-3.05 2.05,3.05, body extent -2.3,-3.3 2.3,3.3, height 0.25
Samtec_TSW-109-07-G-D [mm] "Samtec 100mil, 2x9, 230 mil above insulator"
  rrect6% 1.65x1.65 hole 1.016: 1(-10.16,-1.27)
  round 1.65 hole 1.016: 2(-10.16,1.27) 3(-7.62,-1.27) 4(-7.62,1.27) 5(-5.08,-1.27) 6(-5.08,1.27) 7(-2.54,-1.27) 8(-2.54,1.27) 9(0,-1.27) 10(0,1.27) 11(2.54,-1.27) 12(2.54,1.27) 13(5.08,-1.27) 14(5.08,1.27) 15(7.62,-1.27) 16(7.62,1.27) 17(10.16,-1.27) 18(10.16,1.27)
  silkscreen extent -12.45,-2.54 11.43,2.54, body extent -11.43,-2.54 11.43,2.54, height 8.38
SNT-100-BK-G [mil] "Samtec STEP model"
  round 1 on Mech3: 0(0,0)
  body extent -100,-50 100,50, height 344
SOD-323 [mm] "NXP recommended land pattern"
  rect 0.6x0.6 smd paste-0.05: 1(-1.1,0) 2(1.1,0)
  silkscreen extent -2.06,-0.86 1.53,0.86, body extent -1.3,-0.67 1.3,0.68, height 1.1
SOD-523 [mm] "NXP Semiconductor recommended land pattern, nominal STEP model"
  rect 0.8x0.6 smd paste-0.05: 1(-0.55,0) 2(0.55,0)
  silkscreen extent -1.65,-0.66 1.2,0.66, body extent -0.8,-0.4 0.8,0.4, height 0.72
SOT-23L [mm] "SOT23, 3-Leads, Body 2.9x1.3mm, Pitch 0.95mm, Lead Span 2.5mm, IPC High Density"
  rrect50% 0.8x0.6 smd: 1(-1.1,0.95) 2(-1.1,-0.95) 3(1.1,0)
  silkscreen extent -1.5,-1.5 0.7,1.5, body extent -1.16,-1.45 1.21,1.45, height 1
SRP1038A [mm] "SMD, 2-Leads, Body 11x10mm"
  rect 4.1x3.5 smd: 1(-4.75,0) 2(4.75,0)
  silkscreen extent -5,-5 5,5, body extent -5.2,-5 5.2,5, height 3.75
SSOP28_N [mm] "SOP, 28-Leads, Body 10.2x5.3mm, Pitch 0.65mm, IPC Medium Density"
  oval 2.1x0.45 smd: 1(-3.45,4.225) 2(-3.45,3.575) 3(-3.45,2.925) 4(-3.45,2.275) 5(-3.45,1.625) 6(-3.45,0.975) 7(-3.45,0.325) 8(-3.45,-0.325) 9(-3.45,-0.975) 10(-3.45,-1.625) 11(-3.45,-2.275) 12(-3.45,-2.925) 13(-3.45,-3.575) 14(-3.45,-4.225) 15(3.45,-4.225) 16(3.45,-3.575) 17(3.45,-2.925) 18(3.45,-2.275) 19(3.45,-1.625) 20(3.45,-0.975) 21(3.45,-0.325) 22(3.45,0.325) 23(3.45,0.975) 24(3.45,1.625) 25(3.45,2.275) 26(3.45,2.925) 27(3.45,3.575) 28(3.45,4.225)
  silkscreen extent -3.57,-5.3 2,5.3, body extent -2.7,-5.3 2.7,5.3, height 2
SW_434121025816 [mm] "SMD, 2-Leads, Body 6x3.9mm, Pitch 6.5mm"
  rect 1.5x1.4 smd: 1(-3.25,0) 2(3.25,0)
  silkscreen extent -3,-1.95 3,1.95, body extent -3.65,-1.95 3.65,1.95, height 2.5
SW_B12AP [mm] "NKK Switches"
  rect 1.35x1.35 hole 0.85 paste+0: 1(-1,2.54)
  round 1.35 hole 0.85 paste+0: 2(-1,0) 3(-1,-2.54)
  silkscreen extent -4.27,-4.4 3.4,4.4, body extent -3.4,-4.39 3.4,4.39, height 22.87
TI_Stacked_Overlay_Small [mil]
  silkscreen extent -418,-98 418,98
TSW-104-07-G-S [mm] "Samtec 100mil, 1x4, 230 mil above insulator"
  rrect50% 1.65x1.65 hole 1.016: 1(-3.81,0)
  round 1.65 hole 1.016: 2(-1.27,0) 3(1.27,0) 4(3.81,0)
  body extent -5.08,-1.27 5.08,1.27, height 8.38
WE-MAIA_3015 [mm] "SMD, 2-Leads, Body 3x3mm"
  rect 1.3x3.4 smd: 1(-1.05,0) 2(1.05,0)
  silkscreen extent -0.1,-1.6 0.1,1.6, body extent -1.6,-1.6 1.6,1.6, height 1.5
WEEE_Minimum [mil] "WEEElie bin"
  silkscreen extent -95,-172 99,104

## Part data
C1: library part CMP-0860183-1, "CAP, CERM, 1 µF, 16 V,+/- 10%, X5R, 0603", Cap_Case=0603, Manufacturer=AVX, TempCo=X5R, Tolerance_%=10%, Value2=16V, ValueDisplayed=1µF
C2: library part CMP-0086190-1, "CAP, CERM, 1 µF, 6.3 V,+/- 10%, X7R, AEC-Q200 Grade 1, 0603", Cap_Case=0603, Manufacturer=Kemet, TempCo=X7R, Tolerance_%=10%, Value2=6.3V, ValueDisplayed=1µF
C3: library part CMP-0098402-1, "10 µF ±10% 100V Ceramic Capacitor X6S 1206 (3216 Metric)", Digikey Part Number=445-C3216X6S2A106K160ACCT-ND, Manufacturer=TDK, Mouser Part Number=810-C3216X6S2A106K16, Operating Temperature Range="-55°C to +105°C", TempCo=22%, Temperature Characteristic=X6S, Tolerance_%=10%, ValueDisplayed=10uF
C4: library part CMP-0064935-4, "CAP, CERM, 0.1 uF, 100 V,+/- 10%, X7R, AEC-Q200 Grade 1, 0603", Cap_Case=0603, Manufacturer=MuRata, Supplier Part Number 1=490-13420-1-ND, TempCo=X7R, Tolerance_%=10%, Value1=Unknown, Value2=100V, ValueDisplayed=0.1uF
C5: library part CMP-0007887-2, "CAP, CERM, 0.047 uF, 100 V, +/- 10%, X7R, 0805", Cap_Case=0805, Manufacturer=TDK, Supplier Part Number 1=445-2276-1-ND, TempCo=X7R, Tolerance_%=10%, Value1="0.049089 ohm", Value2=100V, ValueDisplayed=0.047uF
C6: library part CMP-0008959-2, "CAP, CERM, 22 uF, 10 V, +/- 10%, X7R, 1206", Cap_Case=1206, Manufacturer=MuRata, Supplier Part Number 1=490-5309-1-ND, TempCo=X7R, Tolerance_%=10%, Value1=Unknown, Value2=10V, ValueDisplayed=22uF
C7: library part CMP-0006259-2, "CAP, CERM, 0.1 uF, 10 V, +/- 10%, X5R, 0402", Cap_Case=0402, Manufacturer=TDK, Supplier Part Number 1=445-1265-1-ND, TempCo=X5R, Tolerance_%=10%, Value1=Unknown, Value2=10V, ValueDisplayed=0.1uF
C8 C9 C11: library part CMP-0006862-5, "CAP, CERM, 0.1 uF, 10 V, +/- 10%, X7R, 0603", Cap_Case=0603, Manufacturer=Kemet, Supplier Part Number 1=399-1095-1-ND, TempCo=X7R, Tolerance_%=10%, Value1=Unknown, Value2=10V, ValueDisplayed=0.1uF
C10: library part CMP-0007498-4, "CAP, CERM, 4.7 uF, 10 V, +/- 20%, X7R, 0603", Cap_Case=0603, Manufacturer=MuRata, TempCo=X7R, Tolerance_%=20%, Value1=Unknown, Value2=10V, ValueDisplayed=4.7uF
C12: library part CMP-0006826-4, "CAP, CERM, 1000 pF, 16 V, +/- 10%, X7R, 0603", Cap_Case=0603, Manufacturer="Wurth Elektronik", Supplier Part Number 1=710-885012206034, TempCo=X7R, Tolerance_%=10%, Value1=Unknown, Value2=16V, ValueDisplayed=1000pF
C13: library part CMP-0007730-2, "CAP, CERM, 1 uF, 50 V, +/- 10%, X7R, 0805", Cap_Case=0805, Manufacturer=Kemet, Supplier Part Number 1=399-7409-1-ND, TempCo=X7R, Tolerance_%=10%, Value1=Unknown, Value2=50V, ValueDisplayed=1uF
C14: library part CMP-0009912-2, "CAP, AL, 330 uF, 63 V, +/- 20%, AEC-Q200 Grade 2, TH", Cap_Case=12.5x20mm, Manufacturer=Chemi-Con, Supplier Part Number 1=565-2043-ND, Tolerance_%=20%, Value1=Unknown, Value2=63V, ValueDisplayed=330uF
C15 C22: library part CMP-0008970-2, "CAP, CERM, 1 uF, 100 V, +/- 10%, X7R, 1206", Cap_Case=2220, Manufacturer=MuRata, Supplier Part Number 1=490-3909-1-ND, TempCo=X7R, Tolerance_%=10%, Value1=Unknown, Value2=100V, ValueDisplayed=1uF
C16 C21: library part CMP-0007099-4, "CAP, CERM, 0.1 uF, 100 V, +/- 10%, X7S, AEC-Q200 Grade 1, 0603", Cap_Case=0603, Manufacturer=TDK, Supplier Part Number 1=445-6938-1-ND, TempCo=X7S, Tolerance_%=10%, Value1="0.04959 ohm", Value2=100V, ValueDisplayed=0.1uF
